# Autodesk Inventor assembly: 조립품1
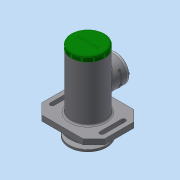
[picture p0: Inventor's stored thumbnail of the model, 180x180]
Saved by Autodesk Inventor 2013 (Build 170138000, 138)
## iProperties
Created: 2017-10
Part Number: 조립품1
Document SubType Name: Assembly
Designer: dgall
Author: dgall
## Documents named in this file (20)
- C:\Users\dgall\Desktop\471007V1014\조립품1.iam
- C:\Users\dgall\Desktop\471007V1014\본체.ipt
- C:\Users\dgall\Desktop\471007V1014\축.ipt
- C:\Users\dgall\Desktop\471007V1014\키 4 x 4 x 18.ipt
- C:\Users\dgall\Desktop\471007V1014\베어링 15 x 35 x 11.ipt
- C:\Users\dgall\Desktop\471007V1014\부시1.ipt
- C:\Users\dgall\Desktop\471007V1014\멈춤링 15 x 1.ipt
- C:\Users\dgall\Desktop\471007V1014\멈춤링 35x1.6.ipt
- C:\Users\dgall\Desktop\471007V1014\부시2.ipt
- C:\Users\dgall\Desktop\471007V1014\와셔 10x21.ipt
- C:\Users\dgall\Desktop\471007V1014\너트 M10.ipt
- C:\Users\dgall\Desktop\471007V1014\사이드 커버.ipt
- 사이드 커버.ipt
- C:\Users\dgall\Desktop\471007V1014\오일 실 15 25 7.ipt
- C:\Users\dgall\Desktop\471007V1014\V-벨트풀리.ipt
- C:\Users\dgall\Desktop\471007V1014\볼트 M4 x 10.ipt
- C:\Users\dgall\Desktop\471007V1014\와셔 4x16.ipt
- C:\Users\dgall\Desktop\471007V1014\탑 커버.ipt
- C:\Users\dgall\Desktop\471007V1014\십자볼트 M3 x 10.ipt
- C:\Users\dgall\Desktop\471007V1014\와셔 3x6.ipt
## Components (2 placed, 2 different names)
1. V-벨트풀리:1
2. ISO 4017 M4 x 10:1
